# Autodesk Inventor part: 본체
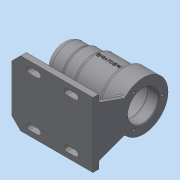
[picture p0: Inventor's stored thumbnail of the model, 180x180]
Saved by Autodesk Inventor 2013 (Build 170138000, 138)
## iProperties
Created: 2017-09
Part Number: 본체
Material: 일반
Document SubType Name: Modeling
Designer: dgall
Density: 1 g/cm^3
Author: dgall
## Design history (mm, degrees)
sketch "스케치1"
  geometry: L1 (0, 0)-(112, 0); L2 (0, 0)-(0, 25); L3 (0, 25)-(25, 25); L4 (25, 25)-(25, 27); L5 (25, 27)-(45, 27); L6 (45, 27)-(45, 30); L7 (45, 30)-(84, 30); L8 (84, 30)-(84, 34); L9 (84, 34)-(112, 34); L10 (112, 34)-(112, 0)
  constraints: 20 end point, 6 parallel, 2 perpendicular, 1 horizontal, 1 vertical
  dimensions: "d0" = 25 distance of L2.end L3.end; "d2" = 45 distance between parallel lines of L6 L2; "d3" = 84 distance between parallel lines of L8 L2; "d4" = 112 distance between parallel lines of L10 L2; "d5" = 50 diameter of L3 L1; "d6" = 54 diameter of L5 L1; "d7" = 60 diameter of L7 L1; "d8" = 68 diameter of L9 L1
revolve "회전1" sketch "스케치1" stored, may be unused: angle "d9" = 90 deg
node "작업 평면9"
  node "작업 평면8"
sketch "스케치7"
  geometry: L1 (-112, 34)-(-112, -34) reference; L2 (-112, 45)-(0, 45); L3 (0, 45)-(0, -45); L4 (0, -45)-(-112, -45); L5 (-112, -45)-(-112, 45); 2 further points
  constraints: 8 end point, 2 parallel, 1 horizontal, 1 horizontal alignment, 1 midpoint, 1 perpendicular, 1 point on line
  dimensions: "d21" = 90 distance of L4.end L2.start; "d23" = 112 distance of L2.start L2.end; "d24" = 45 distance of L2.start point (-112, 0)
extrude "돌출1" join sketch "스케치7" distance "d25" = 8; taper "d26" = 0 deg
sketch "스케치8"
  geometry: L1 (45, -62)-(-45, -62) reference; L2 (-35, -62)-(-21.9, -26.008); L3 (35, -62)-(21.9, -26.008); L4 (-45, -70)-(-45, -62) reference; L5 (45, -70)-(45, -62) reference; L6 (-35, -62)-(35, -62); C1 r 34 at (0, 0) reference; A1 r 34 centre (0, 0) between (-21.9, -26.008) and (21.9, -26.008) reference; A2 r 49.136 centre (0, 17.978) between (-21.9, -26.008) and (21.9, -26.008)
  constraints: 6 end point, 4 point on circle, 1 centre point, 1 equal length, 1 point on line
  dimensions: "d29" = 10 distance from line of L5 L3.start; "d31" = 110 deg angle of L2 L1; "d32" = 110 deg angle of L1 L3; "d33" = 10 distance from line of L2.start L4; "d34" = 49.13585 radius of A2
extrude "돌출2" join sketch "스케치8" distance "d35" = 8; taper "d36" = 0 deg
node "작업 평면10"
sketch "스케치9"
  geometry: L1 (112, -62)-(0, -62) reference; L2 (25, -27)-(45, -27) reference; L3 (22, -62)-(31.378, -27); L4 (112, -62)-(112, -26.008) reference; L5 (22, -62)-(104, -62); L6 (31.378, -27)-(32.372, -23.292); L7 (32.372, -23.292)-(104, -23.292); L8 (104, -23.292)-(104, -62); 2 further points
  constraints: 10 end point, 2 point on line, 1 collinear, 1 parallel, 1 perpendicular
  dimensions: "d37" = 105 deg angle of L3 L1; "d38" = 22 distance of L1.end L3.start; "d41" = 71.62817 distance of L6.end L7.end
extrude "돌출3" join sketch "스케치9" stored distance "d39" = 8; taper "d40" = 0 deg
sketch "스케치10"
  geometry: L1 (0, 0)-(112, 0); L2 (112, -26.008)-(112, 34) reference; L3 (112, 0)-(112, 21); L4 (112, 21)-(97, 21); L5 (97, 21)-(97, 24); L6 (97, 24)-(43, 24); L7 (43, 24)-(43, 21); L8 (43, 21)-(31, 21); L9 (31, 21)-(31, 17.5); L10 (31, 17.5)-(13, 17.5); L11 (13, 17.5)-(13, 16); L12 (13, 16)-(9, 16); L13 (9, 16)-(9, 10.5); L14 (9, 10.5)-(9, 10.5); L15 (6, 7.5)-(6, 0); A1 r 3 centre (9, 7.5) between (9, 10.5) and (6, 7.5); 1 further point
  constraints: 28 end point, 7 parallel, 5 point on line, 3 perpendicular, 2 point on circle, 2 tangent, 1 centre point, 1 collinear, 1 horizontal, 1 vertical
  dimensions: "d42" = 3 distance of L13.end point (6, 10.5); "d44" = 21 diameter of L14 L1; "d45" = 32 diameter of L12 L1; "d46" = 4 distance of L11.end L12.end; "d47" = 18 distance of L9.end L10.end; "d48" = 35 diameter of L10 L1; "d49" = 12 distance of L7.end L8.end; "d50" = 42 diameter of L8 L1; "d51" = 48 diameter of L6 L1; "d52" = 42 diameter of L4 L1; "d53" = 15 distance of L3.end L4.end; "d54" = 54 distance of L5.end L6.end; "d120" = 3 radius of A1
revolve "회전2" sketch "스케치10" stored, may be unused: angle "d55" = 90 deg
fillet "모깎기1" dims "d56" = 9
sketch "스케치11"
  geometry: L1 (80, 8)-(90, 8) reference; L2 (45, 70)-(22.483, 57); L3 (45, 70)-(67.517, 57); L4 (45, 70)-(45, 96); L5 (45, 70)-(45, 96); A1 r 34 centre (45, 70) between (66.9, 43.992) and (23.1, 43.992) reference; A2 r 26 centre (45, 70) between (45, 96) and (22.483, 57); 1 further point
  constraints: 8 end point, 3 point on circle, 2 coincident, 1 centre point, 1 collinear, 1 perpendicular
  dimensions: "d59" = 52 diameter of A2; "d61" = 120 deg angle of L4 L2; "d63" = 120 deg angle of L4 L3
hole "구멍1" sketch "스케치11" at (22.483, 57) diameter "d64" = 3.459; stored, may be unused: countersink angle "d68" = 90 deg, drill point angle "d70" = 118 deg; dims "d65" = 8, "d66" = 4, "d67" = 2, "d69" = 11
chamfer "모따기1" distance "d74" = 12; stored, may be unused: second distance "d75" = 2, angle "d76" = 45 deg
sketch "스케치13"
  geometry: L1 (112, -45)-(112, -35) reference; L2 (112, 45)-(12, 45) reference; L3 (88, -30)-(76, -30); L4 (88, -38)-(76, -38); L5 (36, -30)-(24, -30); L6 (36, -38)-(24, -38); A1 r 4 centre (88, -34) between (88, -38) and (88, -30); A2 r 4 centre (76, -34) between (76, -30) and (76, -38); A3 r 4 centre (36, -34) between (36, -38) and (36, -30); A4 r 4 centre (24, -34) between (24, -30) and (24, -38); 1 further point
  constraints: 8 end point, 8 point on circle, 8 tangent, 4 centre point, 4 parallel, 1 horizontal alignment
  dimensions: "d80" = 24 distance from line of L1 A1.centre; "d81" = 12 distance of A2.centre A1.centre; "d82" = 8 distance between parallel lines of L3 L4; "d83" = 34 vertical distance of point (0, 0) A2.centre; "d84" = 40 distance of A3.centre A2.centre; "d85" = 8 diameter of A3; "d86" = 12 distance of A3.centre A4.centre
extrude "돌출4" cut sketch "스케치13" stored distance "d87" = 8; taper "d88" = 0 deg
extrude "돌출5" cut sketch "스케치13" distance "d89" = 8; taper "d90" = 0 deg
node "작업 평면11"
sketch "스케치14"
  geometry: L1 (112, -26.008)-(112, 34) reference; 2 further points
  constraints: 1 horizontal alignment, 1 other
  dimensions: "d92" = 48 distance from line of L1 point (64, 0)
feature "엠보싱1" sketch "스케치14" dims "d0" = 25, "d2" = 45, "d3" = 84, "d4" = 112, "d5" = 50, "d6" = 54, "d7" = 60, "d8" = 68, "d25" = 8, "d26" = 0, "d93" = 0.5, "d94" = 0
chamfer "모따기2" distance "d101" = 1; stored, may be unused: second distance "d102" = 2, angle "d103" = 45 deg
fillet "모깎기9" dims "d105" = 0.3
fillet "모깎기11" dims "d107" = 3
fillet "모깎기19" dims "d115" = 3
fillet "모깎기20" dims "d116" = 3
fillet "모깎기21" dims "d117" = 3
fillet "모깎기22" dims "d118" = 3
fillet "모깎기23" dims "d119" = 3
node "솔리드1"
pattern_circular "원형 패턴1" dims angle "d72" = 360 deg
mirror "대칭1"
other parameters: "d91" = 351
